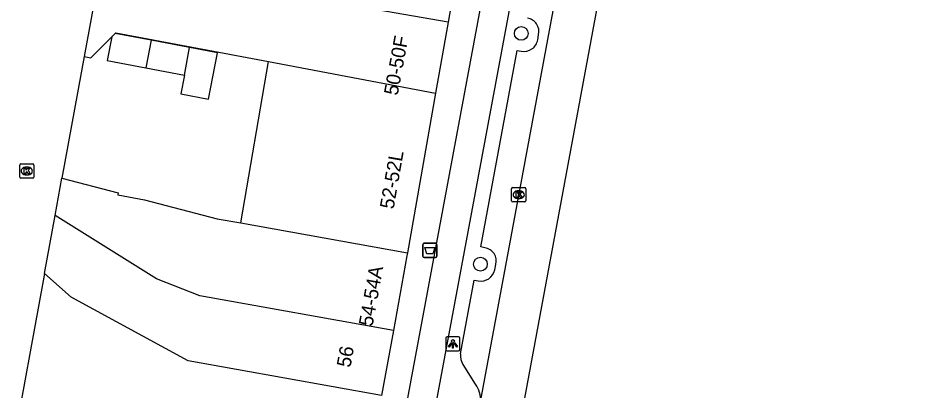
# Model space of a CAD drawing. Extents: x 161402 to 161933, y 381650 to 382313.
# Drawn here: x 161862.2 to 161926.7, y 381952.6 to 381979.1 of the extents above; entities that cross this region are included whole.
import ezdxf

# ---------------------------------------------------------------- set-up
doc = ezdxf.new("R2010")
doc.units = 0
for name, color, linetype in [('IMGEO_Afvalbak', 7, 'Continuous'), ('IMGEO_Boom', 7, 'Continuous'), ('IMGEO_Fietspad_gesloten', 7, 'Continuous'), ('IMGEO_Kolk', 7, 'Continuous'), ('IMGEO_Lichtpunt', 7, 'Continuous'), ('IMGEO_OVBaan_gesloten', 7, 'Continuous'), ('IMGEO_Pand', 7, 'Continuous'), ('IMGEO_Pand_nummerreeks', 7, 'Continuous'), ('IMGEO_Parkeervlak_open', 7, 'Continuous'), ('IMGEO_Rijbaan_lokaal_gesloten', 7, 'Continuous'), ('IMGEO_Rijbaan_lokaal_open', 7, 'Continuous')]:
    doc.layers.add(name, color=color, linetype=linetype)

msp = doc.modelspace()

# ---------------------------------------------------------------- linework, layer by layer
at = {"layer": 'IMGEO_Afvalbak'}
for p, q in [((161890.918, 381962.208), (161890.918, 381963.008)), ((161890.918, 381963.008), (161890.918, 381962.208)), ((161891.018, 381963.108), (161891.808, 381963.108)), ((161891.808, 381963.108), (161891.018, 381963.108)), ((161891.908, 381963.008), (161891.908, 381962.208)), ((161891.908, 381962.208), (161891.908, 381963.008)), ((161891.808, 381962.108), (161891.018, 381962.108)), ((161891.018, 381962.108), (161891.808, 381962.108))]:
    msp.add_line(p, q, dxfattribs=at)
msp.add_lwpolyline([(161891.061, 381962.822), (161891.765, 381962.822), (161891.616, 381962.352), (161891.21, 381962.352), (161891.061, 381962.822)], dxfattribs=at)
for centre, start, end in [((161891.018, 381963.008), 90, 180), ((161891.018, 381963.008), 90, 180), ((161891.808, 381963.008), 0, 90), ((161891.808, 381963.008), 360, 90), ((161891.018, 381962.208), 180, 270), ((161891.018, 381962.208), 180, 270), ((161891.808, 381962.208), 270, 0), ((161891.808, 381962.208), 270, 0)]:
    msp.add_arc(centre, 0.1, start, end, dxfattribs=at)
at = {"layer": 'IMGEO_Boom'}
for centre in [(161897.888, 381978.002), (161894.996, 381961.627)]:
    msp.add_circle(centre, 0.489, dxfattribs=at)
at = {"layer": 'IMGEO_Fietspad_gesloten'}
for points in [[(161869.899, 381834.602), (161881.54, 381896.271), (161882.623, 381902.093), (161888.398, 381933.147), (161890.059, 381942.083), (161900.83, 382000), (161908.061, 382038.88), (161912.039, 382060.567)], [(161887.89, 381941.593), (161898.752, 382000), (161905.702, 382037.375), (161910.061, 382061.001)]]:
    msp.add_lwpolyline(points, dxfattribs=at)
at = {"layer": 'IMGEO_Kolk'}
for p, q in [((161862.352, 381967.813), (161862.352, 381968.665)), ((161862.427, 381968.739), (161863.279, 381968.739)), ((161862.84, 381968.519), (161862.865, 381968.519)), ((161863.353, 381968.665), (161863.353, 381967.813)), ((161863.279, 381967.739), (161862.427, 381967.739)), ((161862.863, 381967.959), (161862.838, 381967.959)), ((161897.282, 381967.057), (161898.134, 381967.057)), ((161897.207, 381966.131), (161897.207, 381966.983)), ((161897.695, 381966.837), (161897.72, 381966.837)), ((161898.208, 381966.983), (161898.208, 381966.131)), ((161898.134, 381966.057), (161897.282, 381966.057)), ((161897.718, 381966.277), (161897.693, 381966.277))]:
    msp.add_line(p, q, dxfattribs=at)
for points in [[(161862.352, 381967.813), (161862.352, 381968.665)], [(161862.427, 381968.739), (161863.279, 381968.739)], [(161862.673, 381968.439), (161862.796, 381968.439), (161862.796, 381968.288), (161862.926, 381968.439), (161863.09, 381968.439), (161862.944, 381968.288), (161863.097, 381968.039), (161862.945, 381968.039), (161862.86, 381968.203), (161862.796, 381968.136), (161862.796, 381968.039), (161862.673, 381968.039), (161862.673, 381968.439)], [(161863.353, 381968.665), (161863.353, 381967.813)], [(161863.279, 381967.739), (161862.427, 381967.739)], [(161897.282, 381967.057), (161898.134, 381967.057)], [(161897.207, 381966.131), (161897.207, 381966.983)], [(161897.528, 381966.757), (161897.651, 381966.757), (161897.651, 381966.606), (161897.781, 381966.757), (161897.945, 381966.757), (161897.799, 381966.606), (161897.952, 381966.357), (161897.8, 381966.357), (161897.715, 381966.521), (161897.651, 381966.454), (161897.651, 381966.357), (161897.528, 381966.357), (161897.528, 381966.757)], [(161898.208, 381966.983), (161898.208, 381966.131)], [(161898.134, 381966.057), (161897.282, 381966.057)]]:
    msp.add_lwpolyline(points, dxfattribs=at)
for centre, start, end in [((161862.429, 381968.663), 91.55205, 178.44795), ((161862.429, 381968.663), 91.55205, 178.44795), ((161863.277, 381968.663), 1.55205, 88.44795), ((161863.277, 381968.663), 1.55205, 88.44795), ((161862.429, 381967.815), 181.55205, 268.44795), ((161862.429, 381967.815), 181.55205, 268.44795), ((161863.277, 381967.815), 271.55205, 358.44795), ((161863.277, 381967.815), 271.55205, 358.44795), ((161897.284, 381966.981), 91.55205, 178.44795), ((161897.284, 381966.981), 91.55205, 178.44795), ((161898.132, 381966.981), 1.55205, 88.44795), ((161898.132, 381966.981), 1.55205, 88.44795), ((161897.284, 381966.133), 181.55205, 268.44795), ((161897.284, 381966.133), 181.55205, 268.44795), ((161898.132, 381966.133), 271.55205, 358.44795), ((161898.132, 381966.133), 271.55205, 358.44795)]:
    msp.add_arc(centre, 0.0765, start, end, dxfattribs=at)
for centre, major_axis, ratio, start_param, end_param in [((161862.839, 381968.239), (-0.387, 0.002), 0.722429, 4.712389, 7.853982), ((161862.864, 381968.239), (-0.39, 0.002), 0.717154, 1.570796, 4.712389), ((161897.694, 381966.557), (-0.387, 0.002), 0.722429, 4.712389, 7.853982), ((161897.719, 381966.557), (-0.39, 0.002), 0.717154, 1.570796, 4.712389)]:
    msp.add_ellipse(centre, major_axis=major_axis, ratio=ratio, start_param=start_param, end_param=end_param, dxfattribs=at)
at = {"layer": 'IMGEO_Lichtpunt'}
for p, q in [((161892.55, 381956.378), (161892.55, 381955.571)), ((161892.55, 381956.378), (161892.55, 381955.571)), ((161893.452, 381956.473), (161892.644, 381956.473)), ((161893.452, 381956.473), (161892.644, 381956.473)), ((161893.546, 381955.571), (161893.546, 381956.378)), ((161893.546, 381955.571), (161893.546, 381956.378)), ((161892.644, 381955.477), (161893.452, 381955.477)), ((161892.644, 381955.477), (161893.452, 381955.477))]:
    msp.add_line(p, q, dxfattribs=at)
for points in [[(161892.924, 381956.042), (161892.963, 381956.014), (161892.775, 381955.752), (161892.737, 381955.779), (161892.924, 381956.042)], [(161893.026, 381955.994), (161893.073, 381955.994), (161893.073, 381955.672), (161893.026, 381955.672), (161893.026, 381955.994)], [(161893.136, 381956.014), (161893.174, 381956.041), (161893.361, 381955.779), (161893.322, 381955.751), (161893.136, 381956.014)]]:
    msp.add_lwpolyline(points, dxfattribs=at)
msp.add_circle((161893.049, 381956.176), 0.0994, dxfattribs=at)
for centre, start, end in [((161892.644, 381956.378), 90, 180), ((161892.644, 381956.378), 90, 180), ((161893.452, 381956.378), 0, 90), ((161893.452, 381956.378), 0, 90), ((161892.644, 381955.571), 180, 270), ((161892.644, 381955.571), 180, 270), ((161893.452, 381955.571), 270, 0), ((161893.452, 381955.571), 270, 360)]:
    msp.add_arc(centre, 0.0946, start, end, dxfattribs=at)
at = {"layer": 'IMGEO_OVBaan_gesloten'}
msp.add_lwpolyline([(161894.174, 381930.698), (161920.066, 382070.485), (161920.568, 382072.989), (161920.797, 382074.121), (161926.695, 382099.95)], dxfattribs=at)
at = {"layer": 'IMGEO_Pand'}
for points in [[(161869.626, 381991.167), (161866.912, 381976.352)], [(161894.351, 381986.526), (161893.665, 381984.233), (161892.707, 381978.796)], [(161892.707, 381978.796), (161880.283, 381980.984)], [(161892.707, 381978.796), (161891.821, 381973.764)], [(161869.113, 381978.001), (161869.163, 381978.052), (161879.974, 381976.006)], [(161866.912, 381976.352), (161867.399, 381976.257), (161868.882, 381977.766)], [(161868.882, 381977.766), (161868.56, 381976.07), (161871.29, 381975.554)], [(161869.113, 381978.001), (161868.882, 381977.766)], [(161871.661, 381977.517), (161869.113, 381978.001)], [(161871.661, 381977.517), (161871.29, 381975.554)], [(161874.391, 381976.998), (161871.661, 381977.517)], [(161874.02, 381975.038), (161873.767, 381973.707), (161875.737, 381973.333), (161876.362, 381976.624), (161874.391, 381976.998)], [(161874.02, 381975.038), (161874.391, 381976.998)], [(161871.29, 381975.554), (161874.02, 381975.038)], [(161878.016, 381964.558), (161879.974, 381976.006)], [(161879.974, 381976.006), (161891.821, 381973.764)], [(161891.821, 381973.764), (161889.826, 381962.441)], [(161864.865, 381965.088), (161865.345, 381967.728)], [(161865.345, 381967.728), (161869.324, 381966.69), (161869.297, 381966.539), (161871.19, 381966.203), (161876.349, 381964.857), (161878.016, 381964.558)], [(161864.117, 381960.973), (161864.865, 381965.088)], [(161888.825, 381956.914), (161875.112, 381959.372), (161872.033, 381960.597), (161864.865, 381965.088)], [(161878.016, 381964.558), (161889.826, 381962.441)], [(161889.826, 381962.441), (161889.787, 381962.219), (161888.825, 381956.914)], [(161864.117, 381960.973), (161864.023, 381960.454), (161861.825, 381948.441)], [(161887.991, 381952.322), (161874.288, 381954.778), (161866.008, 381959.287), (161864.117, 381960.973)], [(161888.825, 381956.914), (161887.991, 381952.322)]]:
    msp.add_lwpolyline(points, dxfattribs=at)
at = {"layer": 'IMGEO_Parkeervlak_open'}
for points in [[(161899.053, 381977.553), (161899.116, 381977.908)], [(161895.3, 381962.787), (161895.024, 381962.853), (161897.605, 381976.788), (161897.892, 381976.746)], [(161896.015, 381961.233), (161896.083, 381961.611)], [(161893.594, 381955.273), (161894.542, 381960.484), (161894.847, 381960.44)], [(161894.652, 381953.123), (161893.761, 381954.508)]]:
    msp.add_lwpolyline(points, dxfattribs=at)
for centre, radius, start, end in [((161898.185, 381978.134), 0.958, 346.34412, 81.88699), ((161898.094, 381977.694), 0.969, 257.97827, 351.62732), ((161895.194, 381961.868), 0.925, 343.88515, 83.4275), ((161895.022, 381961.439), 1.014, 260.04779, 348.30039), ((161894.744, 381955.123), 1.16, 172.59025, 212.03878), ((161893.209, 381952.069), 1.787, 353.64403, 36.14473)]:
    msp.add_arc(centre, radius, start, end, dxfattribs=at)
at = {"layer": 'IMGEO_Rijbaan_lokaal_gesloten'}
msp.add_lwpolyline([(161917.217, 382071.563), (161910.924, 382037.806), (161903.912, 382000), (161894.985, 381951.871)], dxfattribs=at)
at = {"layer": 'IMGEO_Rijbaan_lokaal_open'}
msp.add_lwpolyline([(161866.912, 381976.352), (161865.345, 381967.728)], dxfattribs=at)

# ---------------------------------------------------------------- texts
at = {"layer": 'IMGEO_Pand_nummerreeks'}
for s, rotation, p in [('50-50F', 79.48643, (161889.128, 381973.559)), ('52-52L', 80.00783, (161888.84, 381965.49)), ('54-54A', 79.72135, (161887.346, 381957.168)), ('56', 79.70613, (161885.781, 381954.255))]:
    msp.add_text(s, height=1, rotation=rotation, dxfattribs=at).set_placement(p)

doc.saveas('drawing.dxf')
